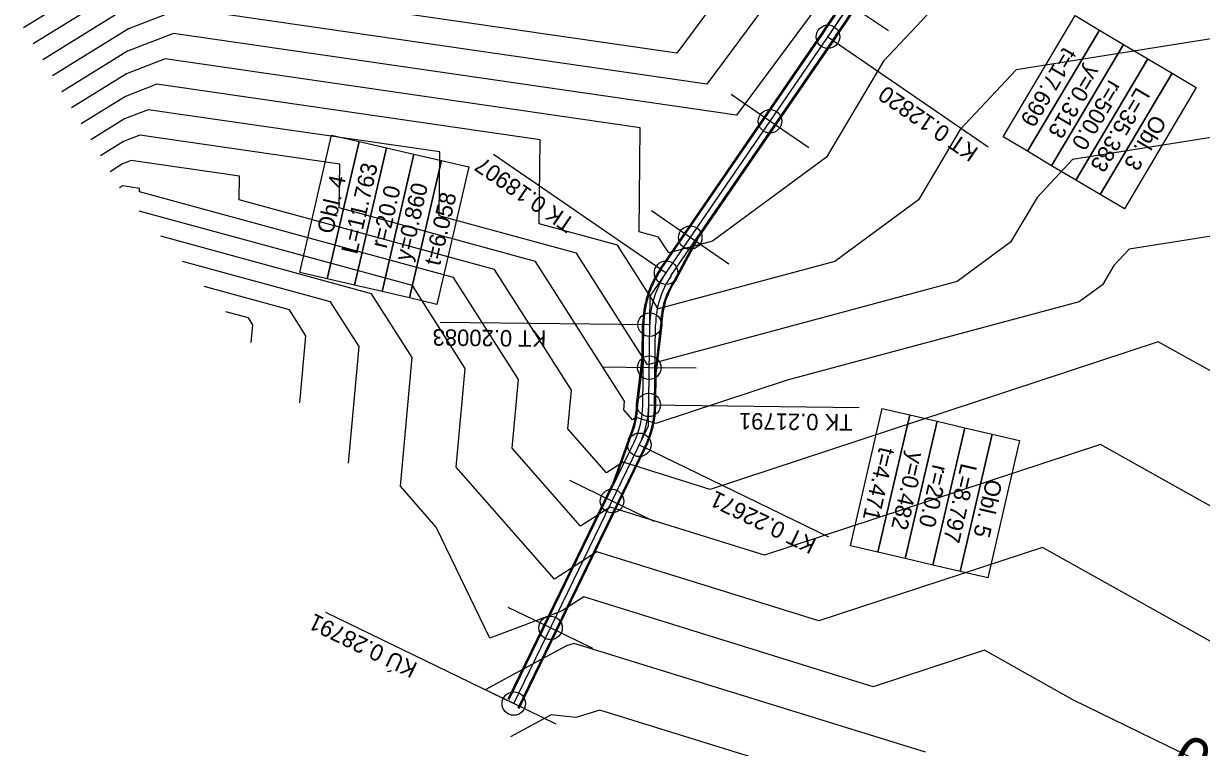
# Model space of a CAD drawing. Extents: x -549394 to -546608, y -1037055 to -1033629.
# Drawn here: x -548982 to -548731.3, y -1034624 to -1034470 of the extents above; entities that cross this region are included whole.
import ezdxf

# ---------------------------------------------------------------- set-up
doc = ezdxf.new("R2010")
doc.units = 0
for name, color, linetype in [('hlavni_vrst', 7, 'Continuous'), ('norm_vrst', 7, 'Continuous'), ('POLYGONY_SITUACE_PO', 7, 'Continuous'), ('u_sirka_1_0m', 7, 'Continuous'), ('x_navrh_C123', 7, 'Continuous'), ('x_osa_C123', 7, 'Continuous'), ('x_popis_oblouky_C123', 7, 'Continuous'), ('x_popis_pricne_rezy_C123', 7, 'Continuous')]:
    doc.layers.add(name, color=color, linetype=linetype)

msp = doc.modelspace()

# ---------------------------------------------------------------- linework, layer by layer
at = {"layer": 'hlavni_vrst'}
for p, q in [((-548959.04, -1034456.71), (-548981.97, -1034470.89)), ((-548782.79, -1034460.78), (-548798.95, -1034478.01)), ((-548951.84, -1034477.49), (-548960.08, -1034480.67)), ((-548850.73, -1034492.13), (-548951.84, -1034477.49)), ((-548798.95, -1034478.01), (-548811.07, -1034498.41)), ((-548960.08, -1034480.67), (-548971.75, -1034487.89)), ((-548850.95, -1034514.29), (-548850.73, -1034492.13)), ((-548811.07, -1034498.41), (-548835.34, -1034516.27)), ((-548961.12, -1034504.64), (-548961.53, -1034504.89)), ((-548960.84, -1034504.53), (-548961.12, -1034504.64)), ((-548957.32, -1034505.04), (-548960.84, -1034504.53)), ((-548957.33, -1034505.81), (-548957.32, -1034505.04)), ((-548890.45, -1034524.01), (-548957.33, -1034505.81)), ((-548846.81, -1034515.42), (-548850.95, -1034514.29)), ((-548844.67, -1034518.77), (-548846.81, -1034515.42)), ((-548835.34, -1034516.27), (-548844.67, -1034518.77)), ((-548876.65, -1034545.68), (-548890.45, -1034524.01)), ((-548934.1, -1034532.6), (-548938.9, -1034531.29)), ((-548938.9, -1034531.29), (-548938.9, -1034531.29)), ((-548933.17, -1034534.06), (-548934.1, -1034532.6)), ((-548933.52, -1034537.84), (-548933.17, -1034534.06)), ((-548877.99, -1034560.29), (-548876.65, -1034545.68)), ((-548863.43, -1034576.88), (-548877.99, -1034560.29)), ((-548752.79, -1034559.55), (-548824.26, -1034583.07)), ((-548695.5, -1034591.58), (-548752.79, -1034559.55)), ((-548857.14, -1034572.85), (-548863.43, -1034576.88)), ((-548824.26, -1034583.07), (-548857.14, -1034572.85))]:
    msp.add_line(p, q, dxfattribs=at)
at = {"layer": 'norm_vrst'}
for p, q in [((-548827.96, -1034456.1), (-548842.93, -1034476.26)), ((-548959.25, -1034461.5), (-548979.93, -1034474.29)), ((-548842.93, -1034476.26), (-548946.44, -1034461.26)), ((-548820.43, -1034461.1), (-548836.58, -1034482.84)), ((-548959.46, -1034466.3), (-548977.88, -1034477.69)), ((-548812.91, -1034466.1), (-548830.24, -1034489.43)), ((-548948.24, -1034466.67), (-548959.67, -1034471.09)), ((-548836.58, -1034482.84), (-548948.24, -1034466.67)), ((-548959.67, -1034471.09), (-548975.84, -1034481.09)), ((-548704.09, -1034469.25), (-548770.74, -1034479.84)), ((-548950.04, -1034472.08), (-548959.87, -1034475.88)), ((-548830.24, -1034489.43), (-548950.04, -1034472.08)), ((-548959.87, -1034475.88), (-548973.8, -1034484.49)), ((-548770.74, -1034479.84), (-548782.61, -1034492.49)), ((-548953.64, -1034482.9), (-548960.29, -1034485.47)), ((-548872.05, -1034494.71), (-548953.64, -1034482.9)), ((-548960.29, -1034485.47), (-548969.71, -1034491.29)), ((-548955.44, -1034488.3), (-548960.5, -1034490.26)), ((-548893.37, -1034497.29), (-548955.44, -1034488.3)), ((-548960.5, -1034490.26), (-548967.66, -1034494.69)), ((-548957.24, -1034493.71), (-548960.71, -1034495.05)), ((-548914.69, -1034499.87), (-548957.24, -1034493.71)), ((-548782.61, -1034492.49), (-548791.5, -1034507.46)), ((-548716.19, -1034492.14), (-548758.7, -1034498.89)), ((-548960.71, -1034495.05), (-548965.62, -1034498.09)), ((-548872.23, -1034512.59), (-548872.05, -1034494.71)), ((-548959.04, -1034499.12), (-548960.91, -1034499.84)), ((-548936, -1034502.46), (-548959.04, -1034499.12)), ((-548893.5, -1034510.9), (-548893.37, -1034497.29)), ((-548758.7, -1034498.89), (-548766.26, -1034506.96)), ((-548960.91, -1034499.84), (-548963.57, -1034501.49)), ((-548914.78, -1034509.2), (-548914.69, -1034499.87)), ((-548936.05, -1034507.5), (-548936, -1034502.46)), ((-548881.73, -1034522.29), (-548936.05, -1034507.5)), ((-548791.5, -1034507.46), (-548809.32, -1034520.57)), ((-548766.26, -1034506.96), (-548771.94, -1034516.5)), ((-548957.37, -1034509.89), (-548957.4, -1034509.89)), ((-548899.18, -1034525.73), (-548957.37, -1034509.89)), ((-548873, -1034520.57), (-548914.78, -1034509.2)), ((-548864.27, -1034518.85), (-548893.5, -1034510.9)), ((-548855.54, -1034517.14), (-548872.23, -1034512.59)), ((-548952.76, -1034515.24), (-548952.77, -1034515.24)), ((-548907.91, -1034527.45), (-548952.76, -1034515.24)), ((-548771.94, -1034516.5), (-548783.3, -1034524.87)), ((-548728.3, -1034515.03), (-548746.65, -1034517.95)), ((-548849.16, -1034542.56), (-548864.27, -1034518.85)), ((-548846.92, -1034530.67), (-548855.54, -1034517.14)), ((-548746.65, -1034517.95), (-548749.92, -1034521.43)), ((-548948.14, -1034520.59), (-548948.15, -1034520.59)), ((-548916.64, -1034529.16), (-548948.14, -1034520.59)), ((-548854.04, -1034550.33), (-548873, -1034520.57)), ((-548809.32, -1034520.57), (-548846.92, -1034530.67)), ((-548749.92, -1034521.43), (-548752.37, -1034525.55)), ((-548865.34, -1034548), (-548881.73, -1034522.29)), ((-548943.52, -1034525.94), (-548943.53, -1034525.94)), ((-548925.37, -1034530.88), (-548943.52, -1034525.94)), ((-548887.95, -1034543.35), (-548899.18, -1034525.73)), ((-548783.3, -1034524.87), (-548849.16, -1034542.56)), ((-548752.37, -1034525.55), (-548757.28, -1034529.16)), ((-548910.56, -1034538.71), (-548916.64, -1034529.16)), ((-548899.26, -1034541.03), (-548907.91, -1034527.45)), ((-548757.28, -1034529.16), (-548819.48, -1034545.87)), ((-548921.87, -1034536.38), (-548925.37, -1034530.88)), ((-548923.18, -1034550.67), (-548921.87, -1034536.38)), ((-548912.84, -1034563.5), (-548910.56, -1034538.71)), ((-548740.46, -1034537.68), (-548835.83, -1034569.07)), ((-548722.7, -1034547.61), (-548740.46, -1034537.68)), ((-548901.77, -1034568.39), (-548899.26, -1034541.03)), ((-548889.88, -1034564.34), (-548887.95, -1034543.35)), ((-548819.48, -1034545.87), (-548847.4, -1034555.06)), ((-548866.1, -1034556.23), (-548865.34, -1034548)), ((-548854.21, -1034552.18), (-548854.04, -1034550.33)), ((-548852.36, -1034554.28), (-548854.21, -1034552.18)), ((-548851.57, -1034553.77), (-548852.36, -1034554.28)), ((-548847.4, -1034555.06), (-548851.57, -1034553.77)), ((-548857.9, -1034565.58), (-548866.1, -1034556.23)), ((-548868.96, -1034588.18), (-548889.88, -1034564.34)), ((-548854.35, -1034563.31), (-548857.9, -1034565.58)), ((-548835.83, -1034569.07), (-548854.35, -1034563.31)), ((-548894.14, -1034577.09), (-548901.77, -1034568.39)), ((-548882.73, -1034600.74), (-548894.14, -1034577.09)), ((-548765.13, -1034581.42), (-548812.69, -1034597.08)), ((-548727, -1034602.74), (-548765.13, -1034581.42)), ((-548859.93, -1034582.39), (-548868.96, -1034588.18)), ((-548812.69, -1034597.08), (-548859.93, -1034582.39)), ((-548862.71, -1034591.94), (-548867.51, -1034595.01)), ((-548801.12, -1034611.08), (-548862.71, -1034591.94)), ((-548867.51, -1034595.01), (-548882.73, -1034600.74)), ((-548864.76, -1034601.89), (-548866.39, -1034602.39)), ((-548790.03, -1034624.96), (-548864.76, -1034601.89)), ((-548866.39, -1034602.39), (-548877.21, -1034608.2)), ((-548777.46, -1034603.3), (-548801.12, -1034611.08)), ((-548758.49, -1034613.9), (-548777.46, -1034603.3)), ((-548877.21, -1034608.2), (-548883.58, -1034611.63)), ((-548727.25, -1034629.19), (-548758.49, -1034613.9)), ((-548859.33, -1034616.05), (-548864.44, -1034617.62)), ((-548825.89, -1034626.38), (-548859.33, -1034616.05)), ((-548869.69, -1034617.07), (-548878.35, -1034621.74)), ((-548864.44, -1034617.62), (-548869.69, -1034617.07))]:
    msp.add_line(p, q, dxfattribs=at)
at = {"layer": 'POLYGONY_SITUACE_PO'}
for centre in [(-548810.77, -1034472.78), (-548845.21, -1034522.98), (-548848.71, -1034534.03), (-548848.92, -1034551.1), (-548850.92, -1034559.6), (-548877.64, -1034614.65)]:
    msp.add_circle(centre, 2.5, dxfattribs=at)
at = {"layer": 'u_sirka_1_0m'}
for centre in [(-548823.11, -1034490.76), (-548840.08, -1034515.5), (-548848.82, -1034543.2), (-548856.73, -1034571.56), (-548869.82, -1034598.55)]:
    msp.add_circle(centre, 2.5, dxfattribs=at)
at = {"layer": 'x_navrh_C123'}
for p, q in [((-548846.24, -1034522.26), (-548811.8, -1034472.07)), ((-548844.18, -1034523.67), (-548809.74, -1034473.49)), ((-548843.28, -1034524.28), (-548838.52, -1034515.43)), ((-548843.06, -1034524.4), (-548838.31, -1034515.57)), ((-548850.17, -1034551.09), (-548849.96, -1034534.03)), ((-548847.67, -1034551.12), (-548847.46, -1034534.06)), ((-548846.38, -1034534.07), (-548847.58, -1034544.06)), ((-548846.13, -1034534.1), (-548847.33, -1034544.06)), ((-548851.5, -1034551.05), (-548850.3, -1034541.09)), ((-548851.25, -1034551.08), (-548850.05, -1034541.09)), ((-548878.61, -1034613.78), (-548852.05, -1034559.05)), ((-548853.25, -1034558.49), (-548856.64, -1034567.94)), ((-548853.02, -1034558.58), (-548856.41, -1034568.05)), ((-548876.68, -1034615.54), (-548849.8, -1034560.14))]:
    msp.add_line(p, q, dxfattribs=at)
for points in [[(-548846.44, -1034522.12), (-548812.01, -1034471.93)], [(-548838.31, -1034515.57), (-548809.54, -1034473.63)], [(-548850.3, -1034541.09), (-548850.21, -1034534.02)], [(-548847.42, -1034551.12), (-548847.33, -1034544.06)], [(-548876.48, -1034615.71), (-548849.57, -1034560.25)], [(-548878.8, -1034613.61), (-548856.64, -1034567.94)]]:
    msp.add_lwpolyline(points, dxfattribs=at)
for centre, radius, start, end in [((-549223.06, -1034189.9), 498.5, 325.5454, 329.6), ((-549223.06, -1034189.9), 498.75, 325.5454, 329.6), ((-549223.06, -1034189.9), 501.25, 325.5454, 329.6), ((-549223.06, -1034189.9), 501.5, 325.5454, 329.6), ((-548828.71, -1034534.28), 21.5, 145.5454, 179.3159), ((-548828.71, -1034534.28), 21.25, 145.5454, 179.3159), ((-548828.71, -1034534.28), 18.75, 145.5454, 179.3159), ((-548828.71, -1034534.28), 17.67, 145.5454, 179.3159), ((-548828.71, -1034534.28), 17.42, 145.4579, 179.4034), ((-548868.92, -1034550.87), 17.42, 334.0268, 359.4034), ((-548868.92, -1034550.87), 17.67, 334.1143, 359.3159), ((-548868.92, -1034550.87), 18.75, 334.1143, 359.3159), ((-548868.92, -1034550.87), 21.25, 334.1143, 359.3159), ((-548868.92, -1034550.87), 21.5, 334.1143, 359.3159)]:
    msp.add_arc(centre, radius, start, end, dxfattribs=at)
at = {"layer": 'x_osa_C123'}
for points in [[(-548848.64, -1034527.97), (-548800.76, -1034458.19), (-548765.05, -1034397.32), (-548748.79, -1034373.93), (-548741.12, -1034365.38)], [(-548848.97, -1034555.58), (-548848.64, -1034527.97)], [(-548877.64, -1034614.65), (-548848.97, -1034555.58)]]:
    msp.add_lwpolyline(points, dxfattribs=at)
for centre, radius, start, end in [((-549223.06, -1034189.9), 500, 325.5454, 329.6), ((-548828.71, -1034534.28), 20, 145.5454, 179.3159), ((-548868.92, -1034550.87), 20, 334.1143, 359.3159)]:
    msp.add_arc(centre, radius, start, end, dxfattribs=at)
at = {"layer": 'x_popis_oblouky_C123'}
for points in [[(-548753.01, -1034471.35), (-548768.32, -1034497.14), (-548773.48, -1034494.08), (-548758.17, -1034468.28)], [(-548747.85, -1034474.41), (-548763.16, -1034500.21), (-548768.32, -1034497.14), (-548753.01, -1034471.35)], [(-548742.69, -1034477.47), (-548758, -1034503.27), (-548763.16, -1034500.21), (-548747.85, -1034474.41)], [(-548737.53, -1034480.53), (-548752.84, -1034506.33), (-548758, -1034503.27), (-548742.69, -1034477.47)], [(-548732.37, -1034483.6), (-548747.68, -1034509.39), (-548752.84, -1034506.33), (-548737.53, -1034480.53)], [(-548923.2, -1034522.92), (-548916.41, -1034493.7), (-548910.56, -1034495.06), (-548917.36, -1034524.28)], [(-548917.36, -1034524.28), (-548910.56, -1034495.06), (-548904.72, -1034496.42), (-548911.51, -1034525.64)], [(-548911.51, -1034525.64), (-548904.72, -1034496.42), (-548898.88, -1034497.78), (-548905.67, -1034527)], [(-548905.67, -1034527), (-548898.88, -1034497.78), (-548893.03, -1034499.14), (-548899.83, -1034528.36)], [(-548899.83, -1034528.36), (-548893.03, -1034499.14), (-548887.19, -1034500.49), (-548893.98, -1034529.71)], [(-548793.35, -1034553.23), (-548800.15, -1034582.45), (-548805.99, -1034581.09), (-548799.2, -1034551.87)], [(-548787.51, -1034554.59), (-548794.31, -1034583.81), (-548800.15, -1034582.45), (-548793.35, -1034553.23)], [(-548781.67, -1034555.95), (-548788.46, -1034585.17), (-548794.31, -1034583.81), (-548787.51, -1034554.59)], [(-548775.82, -1034557.3), (-548782.62, -1034586.52), (-548788.46, -1034585.17), (-548781.67, -1034555.95)], [(-548769.98, -1034558.66), (-548776.77, -1034587.88), (-548782.62, -1034586.52), (-548775.82, -1034557.3)]]:
    msp.add_lwpolyline(points, close=True, dxfattribs=at)
for points in [[(-548810.77, -1034472.78), (-548776.66, -1034496.19)], [(-548881.98, -1034497.75), (-548845.21, -1034522.98)], [(-548893.3, -1034533.5), (-548848.71, -1034534.03)], [(-548848.92, -1034551.1), (-548804.14, -1034551.64)], [(-548850.92, -1034559.6), (-548810.64, -1034579.15)], [(-548917.74, -1034595.19), (-548877.64, -1034614.65)]]:
    msp.add_lwpolyline(points, dxfattribs=at)
at = {"layer": 'x_popis_pricne_rezy_C123'}
for points in [[(-548797.85, -1034471.51), (-548806.19, -1034465.98), (-548814.53, -1034460.46)], [(-548814.86, -1034496.42), (-548823.11, -1034490.76), (-548831.35, -1034485.1)], [(-548831.84, -1034521.15), (-548840.08, -1034515.5), (-548848.33, -1034509.84)], [(-548838.82, -1034543.32), (-548848.82, -1034543.2), (-548858.82, -1034543.08)], [(-548847.73, -1034575.92), (-548856.73, -1034571.56), (-548865.72, -1034567.19)], [(-548860.83, -1034602.91), (-548869.82, -1034598.55), (-548878.82, -1034594.18)], [(-548868.64, -1034619.02), (-548877.64, -1034614.65), (-548886.64, -1034610.29)]]:
    msp.add_lwpolyline(points, dxfattribs=at)

# ---------------------------------------------------------------- texts
at = {"layer": 'x_popis_oblouky_C123'}
for s, rotation, p in [('t=17.699', 239.3282, (-548760.6, -1034474.74)), ('y=0.313', 239.3282, (-548755.49, -1034478.58)), ('KT 0.12820', 145.5454, (-548778.5, -1034496.68)), ('r=500.0', 239.3282, (-548750.89, -1034481.72)), ('L=35.383', 239.3282, (-548745.05, -1034483.29)), ('Obl. 3', 239.3282, (-548741.52, -1034489.11)), ('TK 0.18907', 145.5454, (-548864.34, -1034511.81)), ('L=11.763', 76.93, (-548910.99, -1034519.23)), ('Obl. 4', 76.93, (-548916.15, -1034514.9)), ('y=0.860', 76.93, (-548899.65, -1034520.71)), ('r=20.0', 76.93, (-548904.72, -1034517.97)), ('t=6.058', 76.93, (-548893.36, -1034521.69)), ('KT 0.20083', 179.3159, (-548870.69, -1034535.28)), ('TK 0.21791', 179.3159, (-548805.48, -1034553.1)), ('t=4.471', 256.93, (-548799.83, -1034559.89)), ('y=0.482', 256.93, (-548793.53, -1034560.87)), ('r=20.0', 256.93, (-548788.46, -1034563.61)), ('L=8.797', 256.93, (-548782.42, -1034563.34)), ('KT 0.22671', 154.1143, (-548812.96, -1034579.81)), ('Obl. 5', 256.93, (-548777.03, -1034566.69)), ('KÚ 0.28791', 154.1143, (-548897.88, -1034606.18))]:
    msp.add_text(s, height=3.5, rotation=rotation, dxfattribs=at).set_placement(p)
at = {"layer": 'x_popis_pricne_rezy_C123'}
msp.add_text('PŘ 9 km 0.2400', height=9.0627, rotation=154.1143, dxfattribs=at).set_placement((-548656.24, -1034658.77))

doc.saveas('drawing.dxf')
